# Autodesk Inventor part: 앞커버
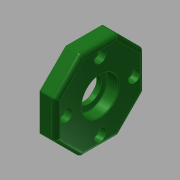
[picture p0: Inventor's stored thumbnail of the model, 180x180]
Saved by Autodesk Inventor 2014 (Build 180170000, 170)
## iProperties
Created: 2015-11
Part Number: 앞커버
Material: 알루미늄 6061
Document SubType Name: Modeling
Designer: mduedu
Density: 1 g/cm^3
Appearance: 매끄러움 - 짙은 산림 녹색
Author: mduedu
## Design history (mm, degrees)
sketch "스케치5" dims "d66" = 60
  geometry: L1 (12.426, 30)-(30, 12.426); L2 (30, 12.426)-(30, -12.426); L3 (30, -12.426)-(12.426, -30); L4 (12.426, -30)-(-12.426, -30); L5 (-12.426, -30)-(-30, -12.426); L6 (-30, -12.426)-(-30, 12.426); L7 (-30, 12.426)-(-12.426, 30); L8 (-12.426, 30)-(12.426, 30); 4 further points
  constraints: 16 end point, 2 coincident, 2 vertical alignment, 1 midpoint, 19 other
extrude "돌출2" new body sketch "스케치5" distance "d67" = 11; taper "d68" = 0 deg
sketch "스케치6"
  geometry: C1 r 16 at (0, 0); 1 further point
  constraints: 1 centre point, 1 coincident
  dimensions: "d69" = 32 diameter of C1
extrude "돌출3" join sketch "스케치6" distance "d70" = 3; taper "d71" = 0 deg
hole "구멍7" diameter "d98" = 25; stored, may be unused: countersink angle "d102" = 90 deg, drill point angle "d104" = 0 deg; dims "d96" = 10, "d97" = 10, "d99" = 6, "d100" = 4, "d101" = 2, "d103" = 3
hole "구멍8" diameter "d107" = 25; stored, may be unused: countersink angle "d111" = 90 deg, drill point angle "d113" = 0 deg; dims "d105" = 10, "d106" = 10, "d108" = 6, "d109" = 4, "d110" = 2, "d112" = 7.7
hole "구멍9" diameter "d116" = 17; stored, may be unused: countersink angle "d120" = 90 deg, drill point angle "d122" = 0 deg; dims "d114" = 10, "d115" = 10, "d117" = 6, "d118" = 4, "d119" = 2, "d121" = 7.7
chamfer "모따기2" distance "d123" = 0.6; stored, may be unused: second distance "d124" = 2, angle "d125" = 30 deg
fillet "모깎기11" dims "d126" = 0.3
fillet "모깎기12" dims "d127" = 1
fillet "모깎기13" dims "d128" = 3
fillet "모깎기14" dims "d129" = 3
fillet "모깎기15" dims "d130" = 0.3
sketch "스케치8" dims "d131" = 46
  geometry: 3 further points
  constraints: 2 vertical alignment, 1 coincident, 2 other
hole "구멍10" sketch "스케치8" at (0, 23) diameter "d132" = 4.5; stored, may be unused: countersink angle "d136" = 90 deg, drill point angle "d138" = 0 deg; dims "d133" = 6, "d134" = 8, "d135" = 4.6, "d137" = 7.7
node "솔리드2"
pattern_circular "원형 패턴4" dims angle "d140" = 360 deg
